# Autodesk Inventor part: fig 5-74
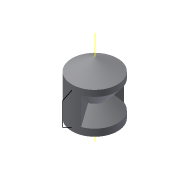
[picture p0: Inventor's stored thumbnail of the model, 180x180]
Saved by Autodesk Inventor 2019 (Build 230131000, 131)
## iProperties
Created: 2004-05
Part Number: fig 5-74
Document SubType Name: Modeling
Designer: CADCIM Technologies
Manufacturer: Standard
Standards Organization: Custom
Density: 1 g/cm^3
Material: Generic
Appearance: Default
Author: CADCIM Technologies
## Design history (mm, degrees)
sketch "Sketch1"
  geometry: L1 (0, -21.51)-(0, 21.51); L2 (0, 21.51)-(-14.639, 13.059); L3 (-14.639, 13.059)-(-14.639, -13.059); L4 (-14.639, -13.059)-(0, -21.51); 2 further points
  constraints: 8 end point, 1 coincident, 1 equal length, 1 midpoint, 1 parallel, 1 vertical, 1 other
  dimensions: "d3" = 120 deg angle of L4 L3
revolve "Revolution1" sketch "Sketch1" stored, may be unused: angle "d0" = 90 deg
workaxis "Work Axis1"
sketch "Sketch2"
  geometry: L1 (-15.658, 10.423)-(-7.144, 0); L2 (-7.144, 0)-(-15.658, -9.738); L3 (-15.658, -9.738)-(-15.658, 10.423); L4 (0, -25.812)-(0, 34.416) reference
  constraints: 6 end point, 1 vertical
revolve "Revolution2" sketch "Sketch2" stored, may be unused: angle "d4" = 140 deg
sketch "Sketch3"
  geometry: L1 (-14.955, 9.983)-(-20.736, 7.191); L2 (-20.736, 7.191)-(-20.736, -7.686); L3 (-20.736, -7.686)-(-15, -10.57); L4 (0, -25.812)-(0, 34.416) reference
  constraints: 6 end point, 1 equal length, 1 vertical
body "Solid1"
